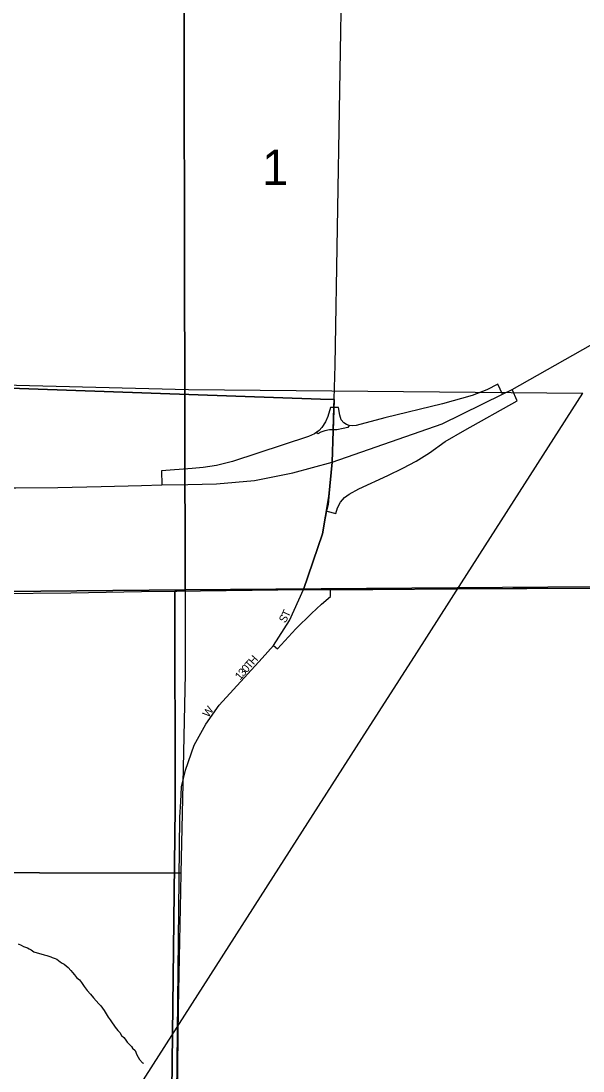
# Model space of a CAD drawing. Extents: x 2010165 to 2382125, y 1060529 to 1407316.
# Drawn here: x 2164031 to 2167540, y 1243143 to 1249702 of the extents above; entities that cross this region are included whole.
import ezdxf

# ---------------------------------------------------------------- set-up
doc = ezdxf.new("R2010")
doc.units = 0
for name, color, linetype in [('GM_X_City_Street', 7, 'Continuous'), ('GM_X_City_Street_Text', 7, 'Continuous'), ('GM_X_Corporation', 7, 'Continuous'), ('GM_X_Interchange_Ramps', 7, 'Continuous'), ('GM_X_Interstate_Route', 7, 'Continuous'), ('GM_X_Minor_River', 7, 'Continuous'), ('GM_X_Rail_Line', 7, 'Continuous'), ('GM_X_Section', 7, 'Continuous'), ('GM_X_Section_Text', 7, 'Continuous'), ('GM_X_State_Route', 7, 'Continuous')]:
    doc.layers.add(name, color=color, linetype=linetype)

msp = doc.modelspace()

# ---------------------------------------------------------------- linework, layer by layer
at = {"layer": 'GM_X_City_Street'}
for points in [[(2165985.8, 1247339.9), (2165992, 1247552), (2166036.5, 1250127.7), (2166040.5, 1250681.1)], [(2165975.2, 1246978), (2165980.1, 1247147.7), (2165984.3, 1247287.7), (2165985.8, 1247339.9)], [(2165961.6, 1246808.8), (2165974.3, 1246946.8), (2165975.2, 1246978)], [(2165795.2, 1246151.4), (2165912.4, 1246498.8), (2165941.4, 1246640.4), (2165950, 1246682.2), (2165956.4, 1246752.4)], [(2165956.4, 1246752.4), (2165961.6, 1246808.8)], [(2165536.1, 1245722.9), (2165607.2, 1245801.3), (2165706.3, 1245957.4), (2165795.2, 1246151.4)], [(2165028.4, 1244825.2), (2165033.5, 1244917.8), (2165057.6, 1245021.7), (2165111.8, 1245179.2), (2165184.1, 1245308.8), (2165268.4, 1245427.8), (2165536.1, 1245722.9)], [(2164984.2, 1241279.2), (2165023, 1244728), (2165028.4, 1244825.2)]]:
    msp.add_lwpolyline(points, dxfattribs=at)
at = {"layer": 'GM_X_Corporation'}
for points in [[(2163019.5, 1247441.3), (2165900.7, 1247340.6), (2165985.7, 1247337.7), (2165974.3, 1246946.8), (2165953.8, 1246731.2), (2165912.4, 1246498.8), (2165795.2, 1246151.4), (2164990.9, 1246140.9), (2164993.1, 1244787.5), (2164951.2, 1241254.6)], [(2168942.5, 1246165), (2166750.6, 1246155.4), (2166227.6, 1246151.5), (2165795.2, 1246151.4), (2165912.4, 1246498.8), (2165953.8, 1246731.2), (2165974.3, 1246946.8), (2165985.7, 1247337.7), (2165900.7, 1247340.6), (2163019.5, 1247441.3)], [(2168837.3, 1237599.9), (2164902.9, 1237581.6), (2164951.2, 1241254.6), (2164993.1, 1244787.5), (2164990.9, 1246140.9), (2165795.2, 1246151.4), (2166227.6, 1246151.5), (2166750.6, 1246155.4), (2168942.5, 1246165)]]:
    msp.add_lwpolyline(points, dxfattribs=at)
at = {"layer": 'GM_X_Interchange_Ramps'}
for points in [[(2167036.8, 1247371.1), (2167008.6, 1247434.1), (2166939, 1247398.1), (2166847, 1247362.2), (2166662.9, 1247310.5), (2166303.6, 1247222.9), (2166124, 1247175.8), (2166101.3, 1247172.8), (2166079.1, 1247175.8), (2166064.2, 1247181.2), (2166046.9, 1247192.3), (2166029.7, 1247211.7), (2166020.7, 1247240.9), (2166013.8, 1247287.5), (2165984.3, 1247287.7)], [(2165941.4, 1246640.4), (2165996, 1246625.5), (2166007.2, 1246661.4), (2166025.2, 1246697.3), (2166049.9, 1246726.5), (2166079.1, 1246746.8), (2166139.7, 1246780.4), (2166321.6, 1246863.5), (2166415.9, 1246908.5), (2166498.9, 1246953.4), (2166582.1, 1247005.1), (2166678.6, 1247074.7), (2166802.1, 1247146.6), (2167129.9, 1247328.5), (2167097.4, 1247401)], [(2165984.3, 1247287.7), (2165963.5, 1247287.9), (2165946.1, 1247232.3), (2165931.8, 1247198.9), (2165908.5, 1247162.3), (2165892.7, 1247144.3), (2165877.2, 1247133.5), (2165863.5, 1247124.1), (2165825.4, 1247106.1), (2165351.6, 1246951.1), (2165250.6, 1246926.4), (2165167.5, 1246913), (2165100.2, 1246906.2), (2164907.1, 1246892.7), (2164910.1, 1246804.1)], [(2165980.1, 1247147.7), (2165956.7, 1247147.8), (2165928.4, 1247142.1), (2165902, 1247133.8), (2165883.8, 1247124.1), (2165877.2, 1247133.5)], [(2166079.1, 1247175.8), (2166072.4, 1247162.3), (2166042.2, 1247156.8), (2166003.4, 1247147.5), (2165980.1, 1247147.7)], [(2165607.2, 1245801.3), (2165631.7, 1245779.5), (2165746, 1245904.4), (2165844.3, 1246001.1), (2165907.9, 1246060), (2165963.1, 1246106.7), (2165963.3, 1246152.1)]]:
    msp.add_lwpolyline(points, dxfattribs=at)
at = {"layer": 'GM_X_Interstate_Route'}
for points in [[(2165974.3, 1246946.8), (2166660.7, 1247185.1), (2167036.8, 1247371.1), (2167097.4, 1247401), (2167697.4, 1247739.1), (2168367.4, 1248113.2)], [(2165071.9, 1246807.6), (2165251.5, 1246811.4), (2165487.9, 1246832.3), (2165728.2, 1246879.3), (2165974.3, 1246946.8)], [(2163079.6, 1246789.3), (2163377.9, 1246788.5), (2163770.5, 1246786), (2163999.1, 1246786.8), (2164261.6, 1246787.8), (2164532.1, 1246794.8), (2164782.6, 1246799.7), (2164910.1, 1246804.1), (2165071.9, 1246807.6)]]:
    msp.add_lwpolyline(points, dxfattribs=at)
at = {"layer": 'GM_X_Minor_River'}
for points in [[(2164012, 1243937), (2164032.2, 1243929.3), (2164046.4, 1243921.6), (2164058.6, 1243915.8), (2164070.7, 1243912), (2164080.8, 1243906.2), (2164095, 1243900.4), (2164111.3, 1243888.7), (2164175.8, 1243869.9), (2164192, 1243864.2), (2164204.1, 1243860.4), (2164216.2, 1243856.6), (2164226.3, 1243852.8), (2164244.5, 1243845.1), (2164254.6, 1243841.3), (2164275, 1243825.6), (2164287.2, 1243817.8), (2164299.3, 1243810), (2164313.6, 1243800.3), (2164325.8, 1243790.5), (2164342.2, 1243770.7), (2164352.5, 1243758.9), (2164364.8, 1243745), (2164377.1, 1243727.2), (2164395.5, 1243713.5)], [(2164395.5, 1243713.5), (2164407.8, 1243695.7), (2164424.3, 1243671.9), (2164444.9, 1243646.2), (2164465.4, 1243622.5), (2164483.8, 1243600.8), (2164500.3, 1243581.1), (2164516.6, 1243563.3), (2164528.9, 1243549.5), (2164539.2, 1243535.7), (2164549.5, 1243521.8), (2164562, 1243500), (2164574.4, 1243480.1), (2164586.7, 1243462.3), (2164599.1, 1243444.5), (2164611.4, 1243428.7), (2164619.7, 1243416.8), (2164627.9, 1243406.9), (2164636.1, 1243397), (2164648.4, 1243383.2), (2164658.8, 1243365.3), (2164673.1, 1243351.6), (2164681.3, 1243341.7), (2164693.7, 1243323.9), (2164720.3, 1243296.3), (2164726.5, 1243286.4), (2164742.8, 1243270.6), (2164753.3, 1243244.7), (2164769.9, 1243215), (2164788.4, 1243195.2), (2164796.5, 1243191.4)]]:
    msp.add_lwpolyline(points, dxfattribs=at)
at = {"layer": 'GM_X_Rail_Line'}
for points in [[(2163338, 1247444), (2165077.2, 1247400.9), (2167540, 1247377.8)], [(2152659, 1224128.4), (2152739.6, 1224246.9), (2152909.8, 1224516.9), (2153135.7, 1224869.5), (2153696.1, 1225746.1), (2153852.4, 1225988.7), (2154336.9, 1226746.4), (2154804.9, 1227475), (2154949.8, 1227703.5), (2155203.2, 1228100.3), (2155761.5, 1228971.2), (2156480.3, 1230096.1), (2157742.6, 1232068.2), (2160262.5, 1236005.3), (2160720.5, 1236722.8), (2161364.8, 1237726.8), (2162140.1, 1238942.9), (2162984.3, 1240258.6), (2165607, 1244357.2), (2165822.2, 1244694.3), (2166159.2, 1245221.1), (2166502.4, 1245756.1), (2166780.6, 1246192.6), (2167540, 1247377.8)]]:
    msp.add_lwpolyline(points, dxfattribs=at)
at = {"layer": 'GM_X_Section'}
for points in [[(2163029.2, 1251527.1), (2165045.2, 1251526.2), (2165055.4, 1246148.6), (2163024.8, 1246131)], [(2165045.2, 1251526.2), (2168993.1, 1251524.5), (2168999.8, 1249196.9), (2169019.3, 1246178.7), (2165055.4, 1246148.6)], [(2163024.8, 1246131), (2165055.4, 1246148.6), (2165056, 1245624.9), (2165040.8, 1244939.9), (2165028.5, 1244379.4), (2162378.4, 1244386), (2162427.3, 1246126.4)], [(2162378.4, 1244386), (2165028.5, 1244379.4), (2165025.9, 1244267.5), (2165011.3, 1243537.5), (2165002.8, 1242817.7), (2165000.8, 1242627.9), (2162329.4, 1242638.6)]]:
    msp.add_lwpolyline(points, close=True, dxfattribs=at)
at = {"layer": 'GM_X_State_Route'}
for points in [[(2166540.6, 1246154.5), (2166750.6, 1246155.4), (2167101.3, 1246158.7), (2168998.3, 1246165.1)], [(2161107.1, 1246099.8), (2161839.2, 1246115.1), (2163084.2, 1246121.5), (2163370.3, 1246122.4), (2163403.7, 1246122.8), (2164342, 1246130.6), (2164782.8, 1246138.2), (2165003.5, 1246141.1)], [(2165003.5, 1246141.1), (2165430.1, 1246146.6)], [(2165430.1, 1246146.6), (2165795.2, 1246151.4), (2165803.3, 1246151.4)], [(2165803.3, 1246151.4), (2165963.3, 1246152.1), (2166540.6, 1246154.5)]]:
    msp.add_lwpolyline(points, dxfattribs=at)

# ---------------------------------------------------------------- texts
at = {"layer": 'GM_X_City_Street_Text'}
for s, rotation, p in [('S', 58.93314, (2165679.9, 1245937.3)), ('T', 64.80576, (2165700.7, 1245972.3)), ('T', 48.52962, (2165460, 1245650.6)), ('H', 48.50982, (2165483.3, 1245677)), ('3', 48.49093, (2165419.2, 1245604.4)), ('0', 48.50072, (2165439.6, 1245627.5)), ('1', 48.53501, (2165398.8, 1245581.4)), ('W', 53.97853, (2165200.2, 1245347.5))]:
    msp.add_text(s, height=50, rotation=rotation, dxfattribs=at).set_placement(p)
at = {"layer": 'GM_X_Section_Text'}
msp.add_text('1', height=221, rotation=0.00001, dxfattribs=at).set_placement((2165535.7, 1248677.5))

doc.saveas('drawing.dxf')
